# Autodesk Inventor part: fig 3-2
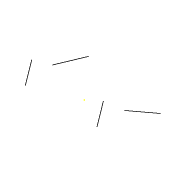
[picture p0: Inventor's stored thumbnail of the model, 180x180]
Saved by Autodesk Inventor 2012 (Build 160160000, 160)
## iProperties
Created: 2011-07
Part Number: fig 3-2
Material: Default
Document SubType Name: Modeling
Designer: CadCim
Density: 1 g/cm^3
Author: CadCim
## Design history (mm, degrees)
sketch "Sketch1"
  geometry: L1 (-29, 4)-(-20, -8); L2 (-22, 7)-(-17, 19); L3 (5, 4)-(14, -8); L4 (13.764, 5.293)-(23.529, 12.617); 1 further point
  constraints: 8 end point, 1 perpendicular, 1 other
